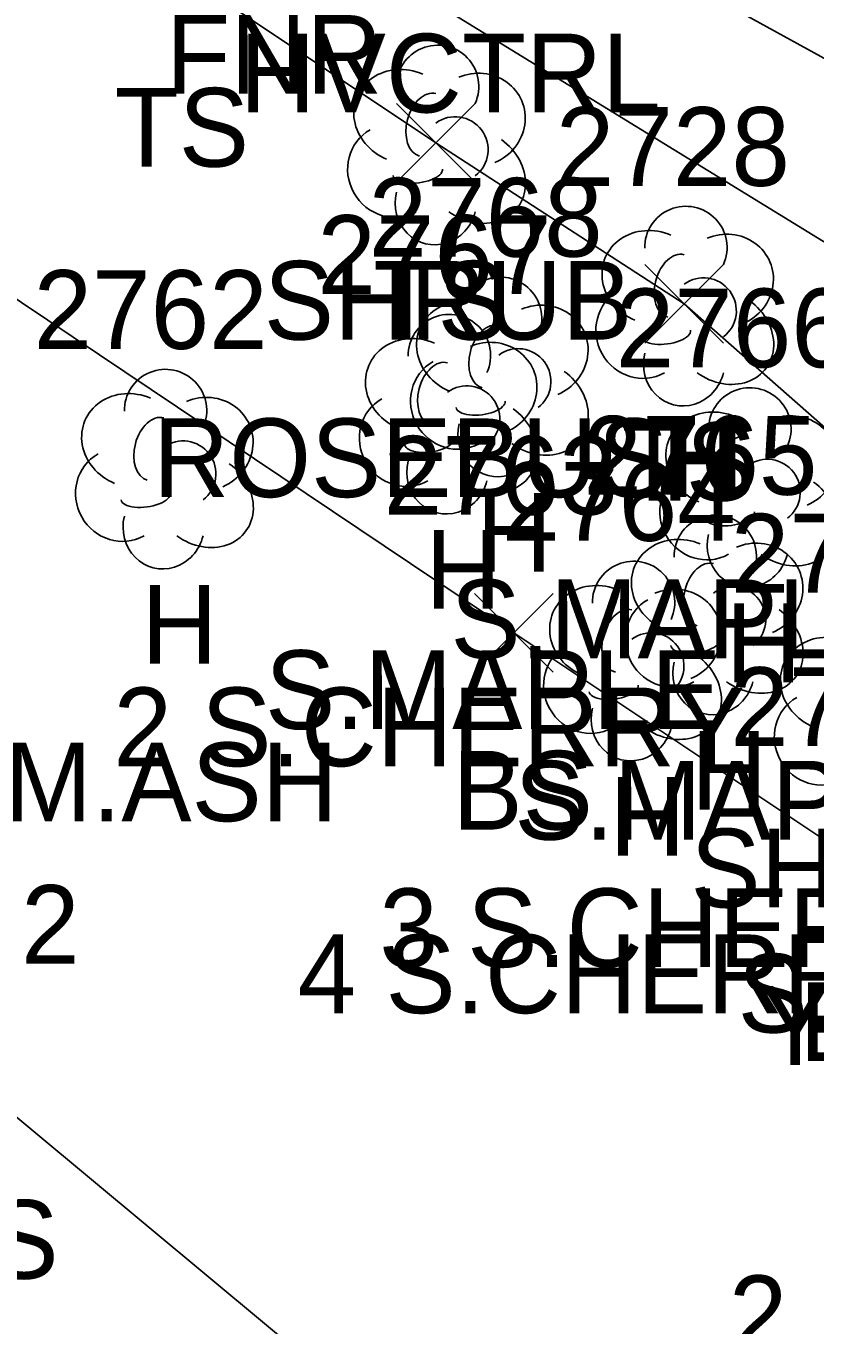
# Model space of a CAD drawing. Extents: x 1499292 to 1501024, y 534584 to 538043.
# Drawn here: x 1499620.23 to 1499640.28, y 537765.66 to 537798.66 of the extents above; entities that cross this region are included whole.
import ezdxf

# ---------------------------------------------------------------- set-up
doc = ezdxf.new("R2010")
doc.units = 0
for name, color, linetype in [('C_A', 7, 'Continuous'), ('L_A', 7, 'Continuous'), ('L_C', 7, 'Continuous'), ('L_I', 7, 'Continuous'), ('L_TIC', 7, 'Continuous'), ('LELB', 7, 'Continuous'), ('LFNC', 7, 'Continuous'), ('LSH', 7, 'Continuous'), ('LTD', 7, 'Continuous'), ('RDG', 7, 'Continuous')]:
    doc.layers.add(name, color=color, linetype=linetype)

msp = doc.modelspace()

# ---------------------------------------------------------------- linework, layer by layer
at = {"layer": 'L_TIC'}
for points in [[(1499629.641, 537794.692), (1499631.641, 537796.692)], [(1499631.641, 537794.692), (1499629.641, 537796.692)], [(1499635.949, 537790.6), (1499637.949, 537792.6)], [(1499637.949, 537790.6), (1499635.949, 537792.6)], [(1499631.622, 537782.246), (1499633.622, 537784.246)], [(1499633.622, 537782.246), (1499631.622, 537784.246)]]:
    msp.add_lwpolyline(points, dxfattribs=at)
at = {"layer": 'LELB'}
for points in [[(1499309.186, 537981.429), (1499342.601, 537967.946), (1499383.002, 537948.454), (1499403.335, 537937.322), (1499425.862, 537923.972), (1499462.056, 537903.885), (1499477.958, 537896.437), (1499498.482, 537885.281), (1499524.089, 537871.298), (1499544.155, 537861.141), (1499587.091, 537836.791), (1499598.177, 537827.35), (1499596, 537821.552), (1499610.739, 537811.692), (1499624.068, 537800.087), (1499630.641, 537795.692), (1499636.949, 537791.6), (1499648.607, 537781.35)], [(1499473.284, 537889.721), (1499498.471, 537879.808), (1499498.645, 537874.964), (1499522.472, 537856.451), (1499547.406, 537847.481), (1499543.068, 537839.362), (1499550.539, 537830.456), (1499554.894, 537825.457), (1499558.691, 537827.698), (1499558.309, 537830.261), (1499565.321, 537832.423), (1499575.95, 537829.995), (1499584.046, 537827.015), (1499587.206, 537819.565), (1499598.435, 537808.198), (1499610.893, 537797.818), (1499632.622, 537783.246), (1499641.436, 537777.369), (1499648.073, 537774.807), (1499656.022, 537768.512), (1499664.288, 537756.487)], [(1499660.39, 537740.632), (1499639.629, 537754.597), (1499618.899, 537771.836), (1499596.925, 537789.586), (1499575.999, 537810.483), (1499560.292, 537815.474)]]:
    msp.add_lwpolyline(points, dxfattribs=at)
at = {"layer": 'LFNC'}
msp.add_lwpolyline([(1499610.739, 537811.692), (1499626.25, 537801.938), (1499645.323, 537790.222), (1499651.803, 537781.891)], dxfattribs=at)
at = {"layer": 'LSH'}
msp.add_line((1499630.641, 537795.692), (1499630.641, 537795.692), dxfattribs=at)
msp.add_line((1499630.641, 537795.692), (1499630.641, 537795.692), dxfattribs=at)
msp.add_arc((1499630.687, 537797.126), 1.047, 335.5272, 180.9563, dxfattribs=at)
for centre, major_axis, ratio, start_param, end_param in [((1499629.849, 537796.358), (1.21, -0.512), 0.895232, 1.570796, 4.712389), ((1499631.682, 537796.275), (-1.141, -0.483), 0.949671, 1.570796, 4.712389), ((1499630.432, 537796.15), (-0.208, -0.792), 0.645439, 3.141593, 6.283185), ((1499631.141, 537795.525), (-0.5, 0.667), 0.989748, 3.141593, 6.283185), ((1499629.557, 537794.983), (0.584, -1.042), 0.959034, 3.141593, 6.283185), ((1499631.641, 537794.859), (-1.09, 0.792), 0.841452, 1.570796, 4.712389), ((1499630.182, 537794.942), (-0.625, -0.083), 0.423636, 0, 3.141593), ((1499630.641, 537794.192), (0.265, 1.061), 0.942809, 1.570796, 4.712389), ((1499640.689, 537781.936), (1.21, -0.512), 0.895232, 1.570796, 4.712389), ((1499640.398, 537780.56), (0.584, -1.042), 0.959034, 3.141593, 6.283185)]:
    msp.add_ellipse(centre, major_axis=major_axis, ratio=ratio, start_param=start_param, end_param=end_param, dxfattribs=at)
at = {"layer": 'LTD'}
for p, q in [((1499636.949, 537791.6), (1499636.949, 537791.6)), ((1499636.949, 537791.6), (1499636.949, 537791.6)), ((1499632.238, 537789.801), (1499632.238, 537789.801)), ((1499632.238, 537789.801), (1499632.238, 537789.801)), ((1499630.938, 537788.855), (1499630.938, 537788.855)), ((1499630.938, 537788.855), (1499630.938, 537788.855)), ((1499623.726, 537787.458), (1499623.726, 537787.458)), ((1499623.726, 537787.458), (1499623.726, 537787.458)), ((1499638.573, 537786.99), (1499638.573, 537786.99)), ((1499638.573, 537786.99), (1499638.573, 537786.99)), ((1499637.695, 537783.753), (1499637.695, 537783.753)), ((1499637.695, 537783.753), (1499637.695, 537783.753)), ((1499635.619, 537782.582), (1499635.619, 537782.582)), ((1499635.619, 537782.582), (1499635.619, 537782.582))]:
    msp.add_line(p, q, dxfattribs=at)
for centre in [(1499636.995, 537793.034), (1499632.285, 537791.235), (1499630.985, 537790.289), (1499623.773, 537788.892), (1499638.62, 537788.424), (1499637.742, 537785.187), (1499635.666, 537784.016)]:
    msp.add_arc(centre, 1.047, 335.5272, 180.9563, dxfattribs=at)
for centre, major_axis, ratio, start_param, end_param in [((1499636.157, 537792.267), (1.21, -0.512), 0.895232, 1.570796, 4.712389), ((1499637.99, 537792.184), (-1.141, -0.483), 0.949671, 1.570796, 4.712389), ((1499636.74, 537792.059), (-0.208, -0.792), 0.645439, 3.141593, 6.283185), ((1499637.449, 537791.434), (-0.5, 0.667), 0.989748, 3.141593, 6.283185), ((1499631.446, 537790.467), (1.21, -0.512), 0.895232, 1.570796, 4.712389), ((1499633.28, 537790.384), (-1.141, -0.483), 0.949671, 1.570796, 4.712389), ((1499635.865, 537790.892), (0.584, -1.042), 0.959034, 3.141593, 6.283185), ((1499637.949, 537790.767), (-1.09, 0.792), 0.841452, 1.570796, 4.712389), ((1499632.03, 537790.259), (-0.208, -0.792), 0.645439, 3.141593, 6.283185), ((1499630.146, 537789.522), (1.21, -0.512), 0.895232, 1.570796, 4.712389), ((1499631.98, 537789.439), (-1.141, -0.483), 0.949671, 1.570796, 4.712389), ((1499636.49, 537790.85), (-0.625, -0.083), 0.423636, 0, 3.141593), ((1499632.738, 537789.634), (-0.5, 0.667), 0.989748, 3.141593, 6.283185), ((1499636.949, 537790.1), (0.265, 1.061), 0.942809, 1.570796, 4.712389), ((1499631.155, 537789.092), (0.584, -1.042), 0.959034, 3.141593, 6.283185), ((1499630.73, 537789.314), (-0.208, -0.792), 0.645439, 3.141593, 6.283185), ((1499633.238, 537788.968), (-1.09, 0.792), 0.841452, 1.570796, 4.712389), ((1499622.935, 537788.124), (1.21, -0.512), 0.895232, 1.570796, 4.712389), ((1499624.768, 537788.041), (-1.141, -0.483), 0.949671, 1.570796, 4.712389), ((1499631.438, 537788.689), (-0.5, 0.667), 0.989748, 3.141593, 6.283185), ((1499629.855, 537788.147), (0.584, -1.042), 0.959034, 3.141593, 6.283185), ((1499631.78, 537789.051), (-0.625, -0.083), 0.423636, 0, 3.141593), ((1499637.781, 537787.656), (1.21, -0.512), 0.895232, 1.570796, 4.712389), ((1499623.518, 537787.916), (-0.208, -0.792), 0.645439, 3.141593, 6.283185), ((1499631.938, 537788.022), (-1.09, 0.792), 0.841452, 1.570796, 4.712389), ((1499639.614, 537787.573), (-1.141, -0.483), 0.949671, 1.570796, 4.712389), ((1499632.238, 537788.301), (0.265, 1.061), 0.942809, 1.570796, 4.712389), ((1499624.226, 537787.291), (-0.5, 0.667), 0.989748, 3.141593, 6.283185), ((1499630.48, 537788.105), (-0.625, -0.083), 0.423636, 0, 3.141593), ((1499638.364, 537787.448), (-0.208, -0.792), 0.645439, 3.141593, 6.283185), ((1499622.643, 537786.749), (0.584, -1.042), 0.959034, 3.141593, 6.283185), ((1499639.073, 537786.823), (-0.5, 0.667), 0.989748, 3.141593, 6.283185), ((1499624.727, 537786.625), (-1.09, 0.792), 0.841452, 1.570796, 4.712389), ((1499630.938, 537787.355), (0.265, 1.061), 0.942809, 1.570796, 4.712389), ((1499637.49, 537786.281), (0.584, -1.042), 0.959034, 3.141593, 6.283185), ((1499639.573, 537786.156), (-1.09, 0.792), 0.841452, 1.570796, 4.712389), ((1499623.268, 537786.708), (-0.625, -0.083), 0.423636, 0, 3.141593), ((1499623.727, 537785.958), (0.265, 1.061), 0.942809, 1.570796, 4.712389), ((1499638.115, 537786.239), (-0.625, -0.083), 0.423636, 0, 3.141593), ((1499636.903, 537784.42), (1.21, -0.512), 0.895232, 1.570796, 4.712389), ((1499638.573, 537785.49), (0.265, 1.061), 0.942809, 1.570796, 4.712389), ((1499638.737, 537784.337), (-1.141, -0.483), 0.949671, 1.570796, 4.712389), ((1499637.487, 537784.212), (-0.208, -0.792), 0.645439, 3.141593, 6.283185), ((1499634.827, 537783.248), (1.21, -0.512), 0.895232, 1.570796, 4.712389), ((1499636.661, 537783.165), (-1.141, -0.483), 0.949671, 1.570796, 4.712389), ((1499638.195, 537783.587), (-0.5, 0.667), 0.989748, 3.141593, 6.283185), ((1499636.612, 537783.045), (0.584, -1.042), 0.959034, 3.141593, 6.283185), ((1499635.411, 537783.04), (-0.208, -0.792), 0.645439, 3.141593, 6.283185), ((1499638.695, 537782.92), (-1.09, 0.792), 0.841452, 1.570796, 4.712389), ((1499636.119, 537782.415), (-0.5, 0.667), 0.989748, 3.141593, 6.283185), ((1499637.237, 537783.003), (-0.625, -0.083), 0.423636, 0, 3.141593), ((1499634.536, 537781.873), (0.584, -1.042), 0.959034, 3.141593, 6.283185), ((1499636.619, 537781.748), (-1.09, 0.792), 0.841452, 1.570796, 4.712389), ((1499637.695, 537782.253), (0.265, 1.061), 0.942809, 1.570796, 4.712389), ((1499635.161, 537781.831), (-0.625, -0.083), 0.423636, 0, 3.141593), ((1499635.619, 537781.082), (0.265, 1.061), 0.942809, 1.570796, 4.712389)]:
    msp.add_ellipse(centre, major_axis=major_axis, ratio=ratio, start_param=start_param, end_param=end_param, dxfattribs=at)
at = {"layer": 'RDG'}
msp.add_lwpolyline([(1499616.247, 537822.183), (1499611.438, 537814.178), (1499627.998, 537804.719), (1499648.228, 537793.601), (1499657.65, 537787.037), (1499661.233, 537780.563), (1499662.782, 537771.708), (1499664.288, 537756.487), (1499660.39, 537740.632), (1499648.725, 537728.571), (1499635.519, 537714.664), (1499643.061, 537703.46), (1499654.084, 537709.775), (1499666.097, 537716.349), (1499687.017, 537701.096), (1499694.358, 537709.594), (1499686.467, 537716.113), (1499685.219, 537725.482), (1499686.936, 537727.795), (1499688.073, 537727.086)], dxfattribs=at)

# ---------------------------------------------------------------- texts
at = {"layer": 'C_A'}
msp.add_text('HVCTRL', height=2, dxfattribs=at).set_placement((1499625.655, 537796.465))
at = {"layer": 'L_A'}
for s, p in [('FNR', (1499623.785, 537796.938)), ('TS', (1499622.477, 537795.087)), ('SHRUB', (1499626.27, 537790.692)), ('TS', (1499629.05, 537790.692)), ('TS', (1499635.358, 537786.6)), ('H', (1499636.382, 537786.6)), ('H', (1499631.671, 537784.801)), ('H', (1499630.371, 537783.855)), ('H', (1499623.16, 537782.458)), ('H', (1499638.006, 537781.99)), ('H', (1499637.128, 537778.753)), ('BS', (1499631.063, 537778.246)), ('H', (1499635.052, 537777.582)), ('SHRUB', (1499637.111, 537776.269)), ('BS', (1499639.877, 537772.369)), ('CS', (1499617.34, 537766.836))]:
    msp.add_text(s, height=2, dxfattribs=at).set_placement(p)
at = {"layer": 'L_C'}
for s, p in [('ROSEBUSH', (1499623.459, 537786.692)), ('S.MAPLE', (1499631.012, 537782.6)), ('S.MAPLE', (1499626.301, 537780.801)), ('2 S.CHERRY', (1499622.45, 537779.855)), ('M.ASH', (1499619.679, 537778.458)), ('S.MAPLE', (1499632.636, 537777.99)), ('3 S.CHERRY', (1499629.207, 537774.753)), ('4 S.CHERRY', (1499627.131, 537773.582)), ('S.MAPLE', (1499638.31, 537773.089)), ('YEW', (1499638.883, 537772.269)), ('2 S.MAPLE AND YEW', (1499638.085, 537764.919))]:
    msp.add_text(s, height=2, dxfattribs=at).set_placement(p)
at = {"layer": 'L_I'}
for s, p in [('2728', (1499633.689, 537794.6)), ('2728', (1499633.689, 537794.6)), ('2768', (1499628.931, 537792.801)), ('2767', (1499627.631, 537791.855)), ('2762', (1499620.419, 537790.458)), ('2766', (1499635.211, 537789.99)), ('2765', (1499634.388, 537786.753)), ('2763', (1499629.315, 537786.246)), ('2764', (1499632.312, 537785.582)), ('2770', (1499638.135, 537784.269)), ('2769', (1499638.121, 537780.369)), ('2782', (1499615.64, 537774.836))]:
    msp.add_text(s, height=2, dxfattribs=at).set_placement(p)

doc.saveas('drawing.dxf')
